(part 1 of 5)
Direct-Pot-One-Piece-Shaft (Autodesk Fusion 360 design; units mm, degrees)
parameter "FrameLength" = 640 comment "Fixed existing outer length"
parameter "FrameWidth" = 190 comment "Fixed existing outer width"
parameter "FrameHeight" = 110 comment "Fixed existing height"
parameter "PivotHeight" = 30 comment "Above frame center"
parameter "LeverTravel" = 100 comment "Stable endpoint to endpoint"
parameter "PrintClearance" = 0.3 comment "Prototype diametral running clearance"
base_mesh_feature "Base Mesh Feature"
ground "Pin1"
work_plane "WorkPlane1" AlongDistance -36 ExtraOffset 0
sketch "Flat load-bearing plate" plane through (-36, 0, 0) normal (1, 0, 0) x axis (0, 0, -1)
  line L1 (-33, -55) -> (-33, -75)
  line L2 (2, -55) -> (-33, -55)
  line L3 (2, 55) -> (2, -55)
  line L4 (-33, 55) -> (2, 55)
  line L5 (-33, 75) -> (-33, 55)
  line L6 (-57, 75) -> (-33, 75)
  line L7 (-57, 32) -> (-57, 75)
  line L8 (-86, 26) -> (-57, 32)
  line L9 (-86, -26) -> (-86, 26)
  line L10 (-57, -32) -> (-86, -26)
  line L11 (-57, -75) -> (-57, -32)
  line L12 (-33, -75) -> (-57, -75)
extrude "Extrude1" new body sketch "Flat load-bearing plate" along normal blind 12
work_plane "WorkPlane2" AlongDistance -37 ExtraOffset 0
sketch "Replaceable bushing seat" plane through (-37, 0, 0) normal (1, 0, 0) x axis (0, 0, -1)
  circle C1 centre (-65, 0) radius 10.15
extrude "Extrude2" cut sketch "Replaceable bushing seat" along normal blind 14
work_plane "WorkPlane3" AlongDistance -37 ExtraOffset 0
sketch "Follower pivot bolt" plane through (-37, 0, 0) normal (1, 0, 0) x axis (0, 0, -1)
  circle C1 centre (-12, -35) radius 2.7
extrude "Extrude3" cut sketch "Follower pivot bolt" along normal blind 14
work_plane "WorkPlane4" AlongDistance -76 ExtraOffset 0
sketch "M5 rail mounting bore" plane through (0, -76, 0) normal (0, 1, 0) x axis (1, 0, 0)
  circle C1 centre (-30, -45) radius 2.7
extrude "Extrude4" cut sketch "M5 rail mounting bore" along normal blind 22
work_plane "WorkPlane5" AlongDistance -55 ExtraOffset 0
sketch "Rail screw tool and washer access" plane through (0, -55, 0) normal (0, 1, 0) x axis (1, 0, 0)
  circle C1 centre (-30, -45) radius 5.3
extrude "Extrude5" cut sketch "Rail screw tool and washer access" along normal blind 12
work_plane "WorkPlane6" AlongDistance 54 ExtraOffset 0
sketch "M5 rail mounting bore (1)" plane through (0, 54, 0) normal (0, 1, 0) x axis (1, 0, 0)
  circle C1 centre (-30, -45) radius 2.7
extrude "Extrude6" cut sketch "M5 rail mounting bore (1)" along normal blind 22
work_plane "WorkPlane7" AlongDistance 43 ExtraOffset 0
sketch "Rail screw tool and washer access (1)" plane through (0, 43, 0) normal (0, 1, 0) x axis (1, 0, 0)
  circle C1 centre (-30, -45) radius 5.3
extrude "Extrude7" cut sketch "Rail screw tool and washer access (1)" along normal blind 12
work_plane "WorkPlane8" AlongDistance -37 ExtraOffset 0
sketch "Spring crossblock attachment" plane through (-37, 0, 0) normal (1, 0, 0) x axis (0, 0, -1)
  circle C1 centre (-44, -59) radius 1.7
extrude "Extrude8" cut sketch "Spring crossblock attachment" along normal blind 14
work_plane "WorkPlane9" AlongDistance -37 ExtraOffset 0
sketch "Spring crossblock attachment (1)" plane through (-37, 0, 0) normal (1, 0, 0) x axis (0, 0, -1)
  circle C1 centre (-44, -51) radius 1.7
extrude "Extrude9" cut sketch "Spring crossblock attachment (1)" along normal blind 14
work_plane "WorkPlane1" AlongDistance 24 ExtraOffset 0
sketch "Flat load-bearing plate" plane through (24, 0, 0) normal (1, 0, 0) x axis (0, 0, -1)
  line L1 (-33, -55) -> (-33, -75)
  line L2 (2, -55) -> (-33, -55)
  line L3 (2, 55) -> (2, -55)
  line L4 (-33, 55) -> (2, 55)
  line L5 (-33, 75) -> (-33, 55)
  line L6 (-57, 75) -> (-33, 75)
  line L7 (-57, 32) -> (-57, 75)
  line L8 (-86, 26) -> (-57, 32)
  line L9 (-86, -26) -> (-86, 26)
  line L10 (-57, -32) -> (-86, -26)
  line L11 (-57, -75) -> (-57, -32)
  line L12 (-33, -75) -> (-57, -75)
extrude "Extrude1" new body sketch "Flat load-bearing plate" along normal blind 12
work_plane "WorkPlane2" AlongDistance 23 ExtraOffset 0
sketch "Replaceable bushing seat" plane through (23, 0, 0) normal (1, 0, 0) x axis (0, 0, -1)
  circle C1 centre (-65, 0) radius 10.15
extrude "Extrude2" cut sketch "Replaceable bushing seat" along normal blind 14
work_plane "WorkPlane3" AlongDistance 23 ExtraOffset 0
sketch "Follower pivot bolt" plane through (23, 0, 0) normal (1, 0, 0) x axis (0, 0, -1)
  circle C1 centre (-12, -35) radius 2.7
extrude "Extrude3" cut sketch "Follower pivot bolt" along normal blind 14
work_plane "WorkPlane4" AlongDistance -76 ExtraOffset 0
sketch "M5 rail mounting bore" plane through (0, -76, 0) normal (0, 1, 0) x axis (1, 0, 0)
  circle C1 centre (30, -45) radius 2.7
extrude "Extrude4" cut sketch "M5 rail mounting bore" along normal blind 22
work_plane "WorkPlane5" AlongDistance -55 ExtraOffset 0
sketch "Rail screw tool and washer access" plane through (0, -55, 0) normal (0, 1, 0) x axis (1, 0, 0)
  circle C1 centre (30, -45) radius 5.3
extrude "Extrude5" cut sketch "Rail screw tool and washer access" along normal blind 12
work_plane "WorkPlane6" AlongDistance 54 ExtraOffset 0
sketch "M5 rail mounting bore (1)" plane through (0, 54, 0) normal (0, 1, 0) x axis (1, 0, 0)
  circle C1 centre (30, -45) radius 2.7
extrude "Extrude6" cut sketch "M5 rail mounting bore (1)" along normal blind 22
work_plane "WorkPlane7" AlongDistance 43 ExtraOffset 0
sketch "Rail screw tool and washer access (1)" plane through (0, 43, 0) normal (0, 1, 0) x axis (1, 0, 0)
  circle C1 centre (30, -45) radius 5.3
extrude "Extrude7" cut sketch "Rail screw tool and washer access (1)" along normal blind 12
work_plane "WorkPlane8" AlongDistance 23 ExtraOffset 0
sketch "Spring crossblock attachment" plane through (23, 0, 0) normal (1, 0, 0) x axis (0, 0, -1)
  circle C1 centre (-44, -59) radius 1.7
extrude "Extrude8" cut sketch "Spring crossblock attachment" along normal blind 14
work_plane "WorkPlane9" AlongDistance 23 ExtraOffset 0
sketch "Spring crossblock attachment (1)" plane through (23, 0, 0) normal (1, 0, 0) x axis (0, 0, -1)
  circle C1 centre (-44, -51) radius 1.7
extrude "Extrude9" cut sketch "Spring crossblock attachment (1)" along normal blind 14
work_plane "WorkPlane1" AlongDistance -36 ExtraOffset 0
sketch "Replaceable journal body" plane through (-36, 0, 0) normal (1, 0, 0) x axis (0, 0, -1)
  circle C1 centre (-65, 0) radius 10.05
extrude "Extrude1" new body sketch "Replaceable journal body" along normal blind 12 bodies "P03 Left flanged journal bush"
work_plane "WorkPlane2" AlongDistance -37.2 ExtraOffset 0
sketch "Axial thrust flange" plane through (-37.2, 0, 0) normal (1, 0, 0) x axis (0, 0, -1)
  circle C1 centre (-65, 0) radius 12.75
extrude "Extrude2" add sketch "Axial thrust flange" along normal blind 1.2
work_plane "WorkPlane3" AlongDistance -38 ExtraOffset 0
sketch "Running journal bore" plane through (-38, 0, 0) normal (1, 0, 0) x axis (0, 0, -1)
  circle C1 centre (-65, 0) radius 6.15
extrude "Extrude3" cut sketch "Running journal bore" along normal blind 15
work_plane "WorkPlane1" AlongDistance 24 ExtraOffset 0
sketch "Replaceable journal body" plane through (24, 0, 0) normal (1, 0, 0) x axis (0, 0, -1)
  circle C1 centre (-65, 0) radius 10.05
extrude "Extrude1" new body sketch "Replaceable journal body" along normal blind 12 bodies "P04 Right bush lower half"
work_plane "WorkPlane2" AlongDistance 36 ExtraOffset 0
sketch "Axial thrust flange" plane through (36, 0, 0) normal (1, 0, 0) x axis (0, 0, -1)
  circle C1 centre (-65, 0) radius 12.75
extrude "Extrude2" add sketch "Axial thrust flange" along normal blind 1.2
work_plane "WorkPlane3" AlongDistance 23 ExtraOffset 0
sketch "Running journal bore" plane through (23, 0, 0) normal (1, 0, 0) x axis (0, 0, -1)
  circle C1 centre (-65, 0) radius 6.15
extrude "Extrude3" cut sketch "Running journal bore" along normal blind 15
work_plane "WorkPlane1" AlongDistance -39.35 ExtraOffset 0
sketch "Axial cap" plane through (-39.35, 0, 0) normal (1, 0, 0) x axis (0, 0, -1)
  circle C1 centre (-65, 0) radius 10
extrude "Extrude1" new body sketch "Axial cap" along normal blind 2 bodies "P06 Shaft retaining cap"
work_plane "WorkPlane2" AlongDistance -39.5 ExtraOffset 0
sketch "M3 cap screw" plane through (-39.5, 0, 0) normal (1, 0, 0) x axis (0, 0, -1)
  circle C1 centre (-65, 0) radius 1.7
extrude "Extrude2" cut sketch "M3 cap screw" along normal blind 2.4
work_plane "WorkPlane1" AlongDistance -7 ExtraOffset 0
sketch "Main lever hub" plane through (-7, 0, 0) normal (1, 0, 0) x axis (0, 0, -1)
  circle C1 centre (-65, 0) radius 22
extrude "Extrude1" new body sketch "Main lever hub" along normal blind 14 bodies "P07 Integral lever rotor and cam carrier"
work_plane "WorkPlane2" AlongDistance -7 ExtraOffset 0
sketch "Continuous reinforced lever stem" plane through (-7, 0, 0) normal (1, 0, 0) x axis (0, 0, -1)
  line L1 (-60, 14) -> (-60, -14)
  line L2 (-95, 11) -> (-60, 14)
  line L3 (-150, 7) -> (-95, 11)
  line L4 (-195, 7) -> (-150, 7)
  line L5 (-195, -7) -> (-195, 7)
  line L6 (-150, -7) -> (-195, -7)
  line L7 (-95, -11) -> (-150, -7)
  line L8 (-60, -14) -> (-95, -11)
extrude "Extrude2" add sketch "Continuous reinforced lever stem" along normal blind 14
work_plane "WorkPlane3" AlongDistance -7 ExtraOffset 0
sketch "Integrated cam carrier fan" plane through (-7, 0, 0) normal (1, 0, 0) x axis (0, 0, -1)
  line L1 (-44.5, 35.507) -> (-65, 0)
  line L2 (-42.6698, 34.3855) -> (-44.5, 35.507)
  line L3 (-40.9008, 33.1697) -> (-42.6698, 34.3855)
  line L4 (-39.1979, 31.863) -> (-40.9008, 33.1697)
  line L5 (-37.5656, 30.4689) -> (-39.1979, 31.863)
  line L6 (-36.0086, 28.9914) -> (-37.5656, 30.4689)
  line L7 (-34.5311, 27.4344) -> (-36.0086, 28.9914)
  line L8 (-33.137, 25.8021) -> (-34.5311, 27.4344)
  line L9 (-31.8303, 24.0992) -> (-33.137, 25.8021)
  line L10 (-30.6145, 22.3302) -> (-31.8303, 24.0992)
  line L11 (-29.493, 20.5) -> (-30.6145, 22.3302)
  line L12 (-28.4687, 18.6136) -> (-29.493, 20.5)
  line L13 (-27.5446, 16.6762) -> (-28.4687, 18.6136)
  line L14 (-26.7232, 14.6931) -> (-27.5446, 16.6762)
  line L15 (-26.0067, 12.6697) -> (-26.7232, 14.6931)
  line L16 (-25.397, 10.6116) -> (-26.0067, 12.6697)
  line L17 (-24.8959, 8.5244) -> (-25.397, 10.6116)
  line L18 (-24.5048, 6.4138) -> (-24.8959, 8.5244)
  line L19 (-24.2246, 4.2857) -> (-24.5048, 6.4138)
  line L20 (-24.0562, 2.1458) -> (-24.2246, 4.2857)
  line L21 (-24, 0) -> (-24.0562, 2.1458)
  line L22 (-24.0562, -2.1458) -> (-24, 0)
  line L23 (-24.2246, -4.2857) -> (-24.0562, -2.1458)
  line L24 (-24.5048, -6.4138) -> (-24.2246, -4.2857)
  line L25 (-24.8959, -8.5244) -> (-24.5048, -6.4138)
  line L26 (-25.397, -10.6116) -> (-24.8959, -8.5244)
  line L27 (-26.0067, -12.6697) -> (-25.397, -10.6116)
  line L28 (-26.7232, -14.6931) -> (-26.0067, -12.6697)
  line L29 (-27.5446, -16.6762) -> (-26.7232, -14.6931)
  line L30 (-28.4687, -18.6136) -> (-27.5446, -16.6762)
  line L31 (-29.493, -20.5) -> (-28.4687, -18.6136)
  line L32 (-30.6145, -22.3302) -> (-29.493, -20.5)
  line L33 (-31.8303, -24.0992) -> (-30.6145, -22.3302)
  line L34 (-33.137, -25.8021) -> (-31.8303, -24.0992)
  line L35 (-34.5311, -27.4344) -> (-33.137, -25.8021)
  line L36 (-36.0086, -28.9914) -> (-34.5311, -27.4344)
  line L37 (-37.5656, -30.4689) -> (-36.0086, -28.9914)
  line L38 (-39.1979, -31.863) -> (-37.5656, -30.4689)
  line L39 (-40.9008, -33.1697) -> (-39.1979, -31.863)
  line L40 (-42.6698, -34.3855) -> (-40.9008, -33.1697)
  line L41 (-44.5, -35.507) -> (-42.6698, -34.3855)
  line L42 (-65, 0) -> (-44.5, -35.507)
extrude "Extrude3" add sketch "Integrated cam carrier fan" along normal blind 14
work_plane "WorkPlane4" AlongDistance -23.6 ExtraOffset 0
sketch "Integral axial locating hub" plane through (-23.6, 0, 0) normal (1, 0, 0) x axis (0, 0, -1)
  circle C1 centre (-65, 0) radius 10
work_plane "WorkPlane5" AlongDistance -24 ExtraOffset 0
sketch "D shaft socket" plane through (-24, 0, 0) normal (1, 0, 0) x axis (0, 0, -1)
  line L1 (-69.6247, 6.65) -> (-60.3753, 6.65)
  arc A1 centre (-65, 0) radius 8.1 clockwise from (-60.3753, 6.65) to (-69.6247, 6.65)
extrude "Extrude5" cut sketch "D shaft socket" along normal blind 48
work_plane "WorkPlane6" AlongDistance 0.3 ExtraOffset 0
sketch "Cam M3 insert pocket" plane through (0.3, 0, 0) normal (1, 0, 0) x axis (0, 0, -1)
  circle C1 centre (-39.5442, 25.4558) radius 1.7
extrude "Extrude6" cut sketch "Cam M3 insert pocket" along normal blind 6.8
work_plane "WorkPlane7" AlongDistance 0.3 ExtraOffset 0
sketch "Cam M3 insert pocket (1)" plane through (0.3, 0, 0) normal (1, 0, 0) x axis (0, 0, -1)
  circle C1 centre (-29, 0) radius 1.7
extrude "Extrude7" cut sketch "Cam M3 insert pocket (1)" along normal blind 6.8
work_plane "WorkPlane8" AlongDistance 0.3 ExtraOffset 0
sketch "Cam M3 insert pocket (2)" plane through (0.3, 0, 0) normal (1, 0, 0) x axis (0, 0, -1)
  circle C1 centre (-39.5442, -25.4558) radius 1.7
extrude "Extrude8" cut sketch "Cam M3 insert pocket (2)" along normal blind 6.8
work_plane "WorkPlane9" AlongDistance -8 ExtraOffset 0
sketch "Grip through bolt" plane through (-8, 0, 0) normal (1, 0, 0) x axis (0, 0, -1)
  circle C1 centre (-180, 0) radius 1.7
extrude "Extrude9" cut sketch "Grip through bolt" along normal blind 16
work_plane "WorkPlane10" AlongDistance -8 ExtraOffset 0
sketch "Grip through bolt (1)" plane through (-8, 0, 0) normal (1, 0, 0) x axis (0, 0, -1)
  circle C1 centre (-190, 0) radius 1.7
extrude "Extrude10" cut sketch "Grip through bolt (1)" along normal blind 16
work_plane "WorkPlane1" AlongDistance 7 ExtraOffset 0
sketch "Roller compensated replaceable cam" plane through (7, 0, 0) normal (1, 0, 0) x axis (0, 0, -1)
  line L1 (-39.4967, 42.2602) -> (-39.6212, 42.3096)
  line L2 (-39.3834, 42.211) -> (-39.4967, 42.2602)
  line L3 (-39.2796, 42.1617) -> (-39.3834, 42.211)
  line L4 (-39.1836, 42.1119) -> (-39.2796, 42.1617)
  line L5 (-39.0932, 42.0608) -> (-39.1836, 42.1119)
  line L6 (-39.0065, 42.0075) -> (-39.0932, 42.0608)
  line L7 (-38.9215, 41.9508) -> (-39.0065, 42.0075)
  line L8 (-38.8363, 41.8895) -> (-38.9215, 41.9508)
  line L9 (-38.7492, 41.8219) -> (-38.8363, 41.8895)
  line L10 (-38.6586, 41.7465) -> (-38.7492, 41.8219)
  line L11 (-38.5633, 41.6619) -> (-38.6586, 41.7465)
  line L12 (-38.4623, 41.5665) -> (-38.5633, 41.6619)
  line L13 (-38.3549, 41.459) -> (-38.4623, 41.5665)
  line L14 (-38.2404, 41.3384) -> (-38.3549, 41.459)
  line L15 (-38.1184, 41.204) -> (-38.2404, 41.3384)
  line L16 (-37.9886, 41.055) -> (-38.1184, 41.204)
  line L17 (-37.8508, 40.8913) -> (-37.9886, 41.055)
  line L18 (-37.7045, 40.7127) -> (-37.8508, 40.8913)
  line L19 (-37.5496, 40.5196) -> (-37.7045, 40.7127)
  line L20 (-37.3856, 40.3123) -> (-37.5496, 40.5196)
  line L21 (-37.2122, 40.0915) -> (-37.3856, 40.3123)
  line L22 (-37.0289, 39.858) -> (-37.2122, 40.0915)
  line L23 (-36.8353, 39.6128) -> (-37.0289, 39.858)
  line L24 (-36.6306, 39.3571) -> (-36.8353, 39.6128)
  line L25 (-36.4145, 39.0923) -> (-36.6306, 39.3571)
  line L26 (-36.1865, 38.82) -> (-36.4145, 39.0923)
  line L27 (-35.9461, 38.5417) -> (-36.1865, 38.82)
  line L28 (-35.6932, 38.2594) -> (-35.9461, 38.5417)
  line L29 (-35.4277, 37.9751) -> (-35.6932, 38.2594)
  line L30 (-35.15, 37.6908) -> (-35.4277, 37.9751)
  line L31 (-34.8607, 37.4087) -> (-35.15, 37.6908)
  line L32 (-34.5606, 37.1307) -> (-34.8607, 37.4087)
  line L33 (-34.2512, 36.859) -> (-34.5606, 37.1307)
  line L34 (-33.934, 36.5953) -> (-34.2512, 36.859)
  line L35 (-33.6109, 36.341) -> (-33.934, 36.5953)
  line L36 (-33.2841, 36.0975) -> (-33.6109, 36.341)
  line L37 (-32.9558, 35.8655) -> (-33.2841, 36.0975)
  line L38 (-32.6282, 35.6454) -> (-32.9558, 35.8655)
  line L39 (-32.3036, 35.4375) -> (-32.6282, 35.6454)
  line L40 (-31.984, 35.2415) -> (-32.3036, 35.4375)
  line L41 (-31.6712, 35.057) -> (-31.984, 35.2415)
  line L42 (-31.3671, 34.8833) -> (-31.6712, 35.057)
  line L43 (-31.073, 34.7197) -> (-31.3671, 34.8833)
  line L44 (-30.7902, 34.5655) -> (-31.073, 34.7197)
  line L45 (-30.52, 34.4197) -> (-30.7902, 34.5655)
  line L46 (-30.263, 34.2816) -> (-30.52, 34.4197)
  line L47 (-30.0201, 34.1506) -> (-30.263, 34.2816)
  line L48 (-29.7919, 34.0259) -> (-30.0201, 34.1506)
  line L49 (-29.5787, 33.9071) -> (-29.7919, 34.0259)
  line L50 (-29.3807, 33.7939) -> (-29.5787, 33.9071)
  line L51 (-29.1982, 33.6858) -> (-29.3807, 33.7939)
  line L52 (-29.0309, 33.5827) -> (-29.1982, 33.6858)
  line L53 (-28.8786, 33.4843) -> (-29.0309, 33.5827)
  line L54 (-28.7406, 33.3906) -> (-28.8786, 33.4843)
  line L55 (-28.6164, 33.3013) -> (-28.7406, 33.3906)
  line L56 (-28.5047, 33.2161) -> (-28.6164, 33.3013)
  line L57 (-28.4046, 33.1346) -> (-28.5047, 33.2161)
  line L58 (-28.3144, 33.0563) -> (-28.4046, 33.1346)
  line L59 (-28.2327, 32.9802) -> (-28.3144, 33.0563)
  line L60 (-28.1577, 32.9052) -> (-28.2327, 32.9802)
  line L61 (-28.0879, 32.8301) -> (-28.1577, 32.9052)
  line L62 (-28.0214, 32.7532) -> (-28.0879, 32.8301)
  line L63 (-27.9569, 32.6728) -> (-28.0214, 32.7532)
  line L64 (-27.893, 32.5869) -> (-27.9569, 32.6728)
  line L65 (-27.8285, 32.4936) -> (-27.893, 32.5869)
  line L66 (-27.7627, 32.3911) -> (-27.8285, 32.4936)
  line L67 (-27.6947, 32.2776) -> (-27.7627, 32.3911)
  line L68 (-27.6241, 32.1514) -> (-27.6947, 32.2776)
  line L69 (-27.5507, 32.0113) -> (-27.6241, 32.1514)
  line L70 (-27.4742, 31.8562) -> (-27.5507, 32.0113)
  line L71 (-27.3945, 31.6853) -> (-27.4742, 31.8562)
  line L72 (-27.3113, 31.4981) -> (-27.3945, 31.6853)
  line L73 (-27.2245, 31.2943) -> (-27.3113, 31.4981)
  line L74 (-27.1338, 31.074) -> (-27.2245, 31.2943)
  line L75 (-27.0388, 30.8373) -> (-27.1338, 31.074)
  line L76 (-26.939, 30.5847) -> (-27.0388, 30.8373)
  line L77 (-26.8337, 30.3166) -> (-26.939, 30.5847)
  line L78 (-26.7223, 30.034) -> (-26.8337, 30.3166)
  line L79 (-26.6038, 29.7375) -> (-26.7223, 30.034)
  line L80 (-26.4775, 29.4284) -> (-26.6038, 29.7375)
  line L81 (-26.3424, 29.1079) -> (-26.4775, 29.4284)
  line L82 (-26.1977, 28.7772) -> (-26.3424, 29.1079)
  line L83 (-26.0425, 28.4382) -> (-26.1977, 28.7772)
  line L84 (-25.8761, 28.0925) -> (-26.0425, 28.4382)
  line L85 (-25.6981, 27.7422) -> (-25.8761, 28.0925)
  line L86 (-25.5084, 27.3893) -> (-25.6981, 27.7422)
  line L87 (-25.3069, 27.0362) -> (-25.5084, 27.3893)
  line L88 (-25.0943, 26.6851) -> (-25.3069, 27.0362)
  line L89 (-24.8713, 26.3382) -> (-25.0943, 26.6851)
  line L90 (-24.6392, 25.9976) -> (-24.8713, 26.3382)
  line L91 (-24.3995, 25.6653) -> (-24.6392, 25.9976)
  line L92 (-24.1539, 25.3428) -> (-24.3995, 25.6653)
  line L93 (-23.9045, 25.0314) -> (-24.1539, 25.3428)
  line L94 (-23.6532, 24.7321) -> (-23.9045, 25.0314)
  line L95 (-23.4022, 24.4455) -> (-23.6532, 24.7321)
  line L96 (-23.1534, 24.1718) -> (-23.4022, 24.4455)
  line L97 (-22.9088, 23.9111) -> (-23.1534, 24.1718)
  line L98 (-22.6701, 23.6631) -> (-22.9088, 23.9111)
  line L99 (-22.4387, 23.4276) -> (-22.6701, 23.6631)
  line L100 (-22.2162, 23.204) -> (-22.4387, 23.4276)
  line L101 (-22.0036, 22.9918) -> (-22.2162, 23.204)
  line L102 (-21.8021, 22.7907) -> (-22.0036, 22.9918)
  line L103 (-21.6123, 22.6001) -> (-21.8021, 22.7907)
  line L104 (-21.435, 22.4197) -> (-21.6123, 22.6001)
  line L105 (-21.2706, 22.2491) -> (-21.435, 22.4197)
  line L106 (-21.1193, 22.088) -> (-21.2706, 22.2491)
  line L107 (-20.9813, 21.9362) -> (-21.1193, 22.088)
  line L108 (-20.8565, 21.7934) -> (-20.9813, 21.9362)
  line L109 (-20.7443, 21.6594) -> (-20.8565, 21.7934)
  line L110 (-20.6444, 21.5337) -> (-20.7443, 21.6594)
  line L111 (-20.556, 21.4159) -> (-20.6444, 21.5337)
  line L112 (-20.478, 21.3055) -> (-20.556, 21.4159)
  line L113 (-20.4094, 21.2014) -> (-20.478, 21.3055)
  line L114 (-20.349, 21.1027) -> (-20.4094, 21.2014)
  line L115 (-20.2954, 21.0079) -> (-20.349, 21.1027)
  line L116 (-20.2475, 20.9154) -> (-20.2954, 21.0079)
  line L117 (-20.2039, 20.8234) -> (-20.2475, 20.9154)
  line L118 (-20.1637, 20.7297) -> (-20.2039, 20.8234)
  line L119 (-20.126, 20.6321) -> (-20.1637, 20.7297)
  line L120 (-20.0901, 20.5286) -> (-20.126, 20.6321)
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extrude "Extrude1" new body sketch "Roller compensated replaceable cam" along normal blind 8 bodies "P08 Cam 7 gates - stable endpoints"
work_plane "WorkPlane2" AlongDistance 6.9 ExtraOffset 0
sketch "Cam screw clearance" plane through (6.9, 0, 0) normal (1, 0, 0) x axis (0, 0, -1)
  circle C1 centre (-39.5442, 25.4558) radius 1.7
extrude "Extrude2" cut sketch "Cam screw clearance" along normal blind 8.2
work_plane "WorkPlane3" AlongDistance 12 ExtraOffset 0
sketch "Cam head recess" plane through (12, 0, 0) normal (1, 0, 0) x axis (0, 0, -1)
  circle C1 centre (-39.5442, 25.4558) radius 3.1
extrude "Extrude3" cut sketch "Cam head recess" along normal blind 3.1
work_plane "WorkPlane4" AlongDistance 6.9 ExtraOffset 0
sketch "Cam screw clearance (1)" plane through (6.9, 0, 0) normal (1, 0, 0) x axis (0, 0, -1)
  circle C1 centre (-29, 0) radius 1.7
extrude "Extrude4" cut sketch "Cam screw clearance (1)" along normal blind 8.2
work_plane "WorkPlane5" AlongDistance 12 ExtraOffset 0
sketch "Cam head recess (1)" plane through (12, 0, 0) normal (1, 0, 0) x axis (0, 0, -1)
  circle C1 centre (-29, 0) radius 3.1
extrude "Extrude5" cut sketch "Cam head recess (1)" along normal blind 3.1
work_plane "WorkPlane6" AlongDistance 6.9 ExtraOffset 0
sketch "Cam screw clearance (2)" plane through (6.9, 0, 0) normal (1, 0, 0) x axis (0, 0, -1)
  circle C1 centre (-39.5442, -25.4558) radius 1.7
extrude "Extrude6" cut sketch "Cam screw clearance (2)" along normal blind 8.2
work_plane "WorkPlane7" AlongDistance 12 ExtraOffset 0
sketch "Cam head recess (2)" plane through (12, 0, 0) normal (1, 0, 0) x axis (0, 0, -1)
  circle C1 centre (-39.5442, -25.4558) radius 3.1
extrude "Extrude7" cut sketch "Cam head recess (2)" along normal blind 3.1
work_plane "WorkPlane1" AlongDistance 7 ExtraOffset 0
sketch "Roller compensated replaceable cam" plane through (7, 0, 0) normal (1, 0, 0) x axis (0, 0, -1)
  line L1 (-40.6423, 42.8316) -> (-40.8055, 42.9534)
  line L2 (-40.4783, 42.705) -> (-40.6423, 42.8316)
  line L3 (-40.3132, 42.5736) -> (-40.4783, 42.705)
  line L4 (-40.1469, 42.4372) -> (-40.3132, 42.5736)
  line L5 (-39.9791, 42.2958) -> (-40.1469, 42.4372)
  line L6 (-39.8097, 42.1493) -> (-39.9791, 42.2958)
  line L7 (-39.6386, 41.9977) -> (-39.8097, 42.1493)
  line L8 (-39.4656, 41.8411) -> (-39.6386, 41.9977)
  line L9 (-39.2906, 41.6794) -> (-39.4656, 41.8411)
  line L10 (-39.1134, 41.5128) -> (-39.2906, 41.6794)
  line L11 (-38.9338, 41.3413) -> (-39.1134, 41.5128)
  line L12 (-38.7519, 41.165) -> (-38.9338, 41.3413)
  line L13 (-38.5674, 40.9842) -> (-38.7519, 41.165)
  line L14 (-38.3803, 40.7991) -> (-38.5674, 40.9842)
  line L15 (-38.1904, 40.6097) -> (-38.3803, 40.7991)
  line L16 (-37.9976, 40.4164) -> (-38.1904, 40.6097)
  line L17 (-37.8019, 40.2195) -> (-37.9976, 40.4164)
  line L18 (-37.6031, 40.0191) -> (-37.8019, 40.2195)
  line L19 (-37.4011, 39.8157) -> (-37.6031, 40.0191)
  line L20 (-37.1958, 39.6094) -> (-37.4011, 39.8157)
  line L21 (-36.9872, 39.4008) -> (-37.1958, 39.6094)
  line L22 (-36.7753, 39.19) -> (-36.9872, 39.4008)
  line L23 (-36.5599, 38.9775) -> (-36.7753, 39.19)
  line L24 (-36.3411, 38.7636) -> (-36.5599, 38.9775)
  line L25 (-36.1189, 38.5488) -> (-36.3411, 38.7636)
  line L26 (-35.8933, 38.3333) -> (-36.1189, 38.5488)
  line L27 (-35.6644, 38.1177) -> (-35.8933, 38.3333)
  line L28 (-35.4322, 37.9021) -> (-35.6644, 38.1177)
  line L29 (-35.197, 37.6871) -> (-35.4322, 37.9021)
  line L30 (-34.9588, 37.473) -> (-35.197, 37.6871)
  line L31 (-34.7178, 37.2602) -> (-34.9588, 37.473)
  line L32 (-34.4743, 37.0489) -> (-34.7178, 37.2602)
  line L33 (-34.2286, 36.8395) -> (-34.4743, 37.0489)
  line L34 (-33.9808, 36.6322) -> (-34.2286, 36.8395)
  line L35 (-33.7314, 36.4274) -> (-33.9808, 36.6322)
  line L36 (-33.4806, 36.2252) -> (-33.7314, 36.4274)
  line L37 (-33.2289, 36.0258) -> (-33.4806, 36.2252)
  line L38 (-32.9765, 35.8294) -> (-33.2289, 36.0258)
  line L39 (-32.7239, 35.6361) -> (-32.9765, 35.8294)
  line L40 (-32.4714, 35.446) -> (-32.7239, 35.6361)
  line L41 (-32.2195, 35.259) -> (-32.4714, 35.446)
  line L42 (-31.9685, 35.0753) -> (-32.2195, 35.259)
  line L43 (-31.7188, 34.8948) -> (-31.9685, 35.0753)
  line L44 (-31.4708, 34.7175) -> (-31.7188, 34.8948)
  line L45 (-31.2249, 34.5432) -> (-31.4708, 34.7175)
  line L46 (-30.9813, 34.3719) -> (-31.2249, 34.5432)
  line L47 (-30.7405, 34.2034) -> (-30.9813, 34.3719)
  line L48 (-30.5027, 34.0377) -> (-30.7405, 34.2034)
  line L49 (-30.2682, 33.8746) -> (-30.5027, 34.0377)
  line L50 (-30.0373, 33.7139) -> (-30.2682, 33.8746)
  line L51 (-29.8103, 33.5555) -> (-30.0373, 33.7139)
  line L52 (-29.5875, 33.3992) -> (-29.8103, 33.5555)
  line L53 (-29.3689, 33.2448) -> (-29.5875, 33.3992)
  line L54 (-29.1548, 33.0923) -> (-29.3689, 33.2448)
  line L55 (-28.9455, 32.9414) -> (-29.1548, 33.0923)
  line L56 (-28.7409, 32.7921) -> (-28.9455, 32.9414)
  line L57 (-28.5413, 32.644) -> (-28.7409, 32.7921)
  line L58 (-28.3468, 32.4972) -> (-28.5413, 32.644)
  line L59 (-28.1574, 32.3515) -> (-28.3468, 32.4972)
  line L60 (-27.9732, 32.2068) -> (-28.1574, 32.3515)
  line L61 (-27.7942, 32.0628) -> (-27.9732, 32.2068)
  line L62 (-27.6204, 31.9196) -> (-27.7942, 32.0628)
  line L63 (-27.4518, 31.7769) -> (-27.6204, 31.9196)
  line L64 (-27.2884, 31.6347) -> (-27.4518, 31.7769)
  line L65 (-27.1301, 31.4927) -> (-27.2884, 31.6347)
  line L66 (-26.9767, 31.351) -> (-27.1301, 31.4927)
  line L67 (-26.8282, 31.2092) -> (-26.9767, 31.351)
  line L68 (-26.6843, 31.0673) -> (-26.8282, 31.2092)
  line L69 (-26.545, 30.925) -> (-26.6843, 31.0673)
  line L70 (-26.4101, 30.7822) -> (-26.545, 30.925)
  line L71 (-26.2793, 30.6387) -> (-26.4101, 30.7822)
  line L72 (-26.1524, 30.4942) -> (-26.2793, 30.6387)
  line L73 (-26.0293, 30.3485) -> (-26.1524, 30.4942)
  line L74 (-25.9096, 30.2013) -> (-26.0293, 30.3485)
  line L75 (-25.7932, 30.0524) -> (-25.9096, 30.2013)
  line L76 (-25.6797, 29.9015) -> (-25.7932, 30.0524)
  line L77 (-25.5691, 29.7482) -> (-25.6797, 29.9015)
  line L78 (-25.461, 29.5923) -> (-25.5691, 29.7482)
  line L79 (-25.3553, 29.4334) -> (-25.461, 29.5923)
  line L80 (-25.2517, 29.2713) -> (-25.3553, 29.4334)
  line L81 (-25.15, 29.1057) -> (-25.2517, 29.2713)
  line L82 (-25.0502, 28.9363) -> (-25.15, 29.1057)
  line L83 (-24.9519, 28.7628) -> (-25.0502, 28.9363)
  line L84 (-24.855, 28.5849) -> (-24.9519, 28.7628)
  line L85 (-24.7595, 28.4024) -> (-24.855, 28.5849)
  line L86 (-24.665, 28.2152) -> (-24.7595, 28.4024)
  line L87 (-24.5716, 28.023) -> (-24.665, 28.2152)
  line L88 (-24.4791, 27.8257) -> (-24.5716, 28.023)
  line L89 (-24.3873, 27.6231) -> (-24.4791, 27.8257)
  line L90 (-24.2961, 27.4152) -> (-24.3873, 27.6231)
  line L91 (-24.2054, 27.2019) -> (-24.2961, 27.4152)
  line L92 (-24.115, 26.9832) -> (-24.2054, 27.2019)
  line L93 (-24.0247, 26.7591) -> (-24.115, 26.9832)
  line L94 (-23.9346, 26.5296) -> (-24.0247, 26.7591)
  line L95 (-23.8442, 26.2947) -> (-23.9346, 26.5296)
  line L96 (-23.7536, 26.0546) -> (-23.8442, 26.2947)
  line L97 (-23.6625, 25.8094) -> (-23.7536, 26.0546)
  line L98 (-23.5707, 25.5592) -> (-23.6625, 25.8094)
  line L99 (-23.478, 25.3041) -> (-23.5707, 25.5592)
  line L100 (-23.3842, 25.0444) -> (-23.478, 25.3041)
  line L101 (-23.2891, 24.7802) -> (-23.3842, 25.0444)
  line L102 (-23.1926, 24.5118) -> (-23.2891, 24.7802)
  line L103 (-23.0943, 24.2394) -> (-23.1926, 24.5118)
  line L104 (-22.9942, 23.9633) -> (-23.0943, 24.2394)
  line L105 (-22.8919, 23.6838) -> (-22.9942, 23.9633)
  line L106 (-22.7873, 23.4012) -> (-22.8919, 23.6838)
  line L107 (-22.6803, 23.1157) -> (-22.7873, 23.4012)
  line L108 (-22.5706, 22.8278) -> (-22.6803, 23.1157)
  line L109 (-22.4581, 22.5379) -> (-22.5706, 22.8278)
  line L110 (-22.3428, 22.2461) -> (-22.4581, 22.5379)
  line L111 (-22.2245, 21.953) -> (-22.3428, 22.2461)
  line L112 (-22.1031, 21.659) -> (-22.2245, 21.953)
  line L113 (-21.9788, 21.3644) -> (-22.1031, 21.659)
  line L114 (-21.8513, 21.0696) -> (-21.9788, 21.3644)
  line L115 (-21.7209, 20.7751) -> (-21.8513, 21.0696)
  line L116 (-21.5876, 20.4811) -> (-21.7209, 20.7751)
  line L117 (-21.4516, 20.1882) -> (-21.5876, 20.4811)
  line L118 (-21.3129, 19.8966) -> (-21.4516, 20.1882)
  line L119 (-21.1718, 19.6067) -> (-21.3129, 19.8966)
  line L120 (-21.0286, 19.3189) -> (-21.1718, 19.6067)
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extrude "Extrude1" new body sketch "Roller compensated replaceable cam" along normal blind 8 bodies "P08 Cam 5 gates - stable endpoints"
work_plane "WorkPlane2" AlongDistance 6.9 ExtraOffset 0
sketch "Cam screw clearance" plane through (6.9, 0, 0) normal (1, 0, 0) x axis (0, 0, -1)
  circle C1 centre (-39.5442, 25.4558) radius 1.7
extrude "Extrude2" cut sketch "Cam screw clearance" along normal blind 8.2
work_plane "WorkPlane3" AlongDistance 12 ExtraOffset 0
sketch "Cam head recess" plane through (12, 0, 0) normal (1, 0, 0) x axis (0, 0, -1)
  circle C1 centre (-39.5442, 25.4558) radius 3.1
extrude "Extrude3" cut sketch "Cam head recess" along normal blind 3.1
work_plane "WorkPlane4" AlongDistance 6.9 ExtraOffset 0
sketch "Cam screw clearance (1)" plane through (6.9, 0, 0) normal (1, 0, 0) x axis (0, 0, -1)
  circle C1 centre (-29, 0) radius 1.7
extrude "Extrude4" cut sketch "Cam screw clearance (1)" along normal blind 8.2
work_plane "WorkPlane5" AlongDistance 12 ExtraOffset 0
sketch "Cam head recess (1)" plane through (12, 0, 0) normal (1, 0, 0) x axis (0, 0, -1)
  circle C1 centre (-29, 0) radius 3.1
extrude "Extrude5" cut sketch "Cam head recess (1)" along normal blind 3.1
work_plane "WorkPlane6" AlongDistance 6.9 ExtraOffset 0
sketch "Cam screw clearance (2)" plane through (6.9, 0, 0) normal (1, 0, 0) x axis (0, 0, -1)
  circle C1 centre (-39.5442, -25.4558) radius 1.7
extrude "Extrude6" cut sketch "Cam screw clearance (2)" along normal blind 8.2
work_plane "WorkPlane7" AlongDistance 12 ExtraOffset 0
sketch "Cam head recess (2)" plane through (12, 0, 0) normal (1, 0, 0) x axis (0, 0, -1)
  circle C1 centre (-39.5442, -25.4558) radius 3.1
extrude "Extrude7" cut sketch "Cam head recess (2)" along normal blind 3.1
work_plane "WorkPlane1" AlongDistance 7 ExtraOffset 0
sketch "Roller compensated replaceable cam" plane through (7, 0, 0) normal (1, 0, 0) x axis (0, 0, -1)
  line L1 (-40.92, 42.0772) -> (-41.1325, 42.2273)
  line L2 (-40.7077, 41.9259) -> (-40.92, 42.0772)
  line L3 (-40.4956, 41.7734) -> (-40.7077, 41.9259)
  line L4 (-40.2838, 41.6199) -> (-40.4956, 41.7734)
  line L5 (-40.0721, 41.4654) -> (-40.2838, 41.6199)
  line L6 (-39.8606, 41.3098) -> (-40.0721, 41.4654)
  line L7 (-39.6492, 41.1532) -> (-39.8606, 41.3098)
  line L8 (-39.4381, 40.9957) -> (-39.6492, 41.1532)
  line L9 (-39.2271, 40.8372) -> (-39.4381, 40.9957)
  line L10 (-39.0163, 40.6779) -> (-39.2271, 40.8372)
  line L11 (-38.8057, 40.5176) -> (-39.0163, 40.6779)
  line L12 (-38.5952, 40.3566) -> (-38.8057, 40.5176)
  line L13 (-38.3849, 40.1947) -> (-38.5952, 40.3566)
  line L14 (-38.1747, 40.032) -> (-38.3849, 40.1947)
  line L15 (-37.9647, 39.8686) -> (-38.1747, 40.032)
  line L16 (-37.7549, 39.7045) -> (-37.9647, 39.8686)
  line L17 (-37.5452, 39.5397) -> (-37.7549, 39.7045)
  line L18 (-37.3357, 39.3742) -> (-37.5452, 39.5397)
  line L19 (-37.1263, 39.2081) -> (-37.3357, 39.3742)
  line L20 (-36.9171, 39.0413) -> (-37.1263, 39.2081)
  line L21 (-36.7081, 38.874) -> (-36.9171, 39.0413)
  line L22 (-36.4992, 38.7061) -> (-36.7081, 38.874)
  line L23 (-36.2905, 38.5376) -> (-36.4992, 38.7061)
  line L24 (-36.082, 38.3687) -> (-36.2905, 38.5376)
  line L25 (-35.8737, 38.1992) -> (-36.082, 38.3687)
  line L26 (-35.6656, 38.0292) -> (-35.8737, 38.1992)
  line L27 (-35.4577, 37.8588) -> (-35.6656, 38.0292)
  line L28 (-35.25, 37.688) -> (-35.4577, 37.8588)
  line L29 (-35.0425, 37.5167) -> (-35.25, 37.688)
  line L30 (-34.8352, 37.3451) -> (-35.0425, 37.5167)
  line L31 (-34.6282, 37.173) -> (-34.8352, 37.3451)
  line L32 (-34.4215, 37.0006) -> (-34.6282, 37.173)
  line L33 (-34.215, 36.8278) -> (-34.4215, 37.0006)
  line L34 (-34.0088, 36.6547) -> (-34.215, 36.8278)
  line L35 (-33.8028, 36.4812) -> (-34.0088, 36.6547)
  line L36 (-33.5972, 36.3074) -> (-33.8028, 36.4812)
  line L37 (-33.392, 36.1333) -> (-33.5972, 36.3074)
  line L38 (-33.187, 35.9589) -> (-33.392, 36.1333)
  line L39 (-32.9825, 35.7842) -> (-33.187, 35.9589)
  line L40 (-32.7783, 35.6093) -> (-32.9825, 35.7842)
  line L41 (-32.5745, 35.434) -> (-32.7783, 35.6093)
  line L42 (-32.3711, 35.2584) -> (-32.5745, 35.434)
  line L43 (-32.1682, 35.0826) -> (-32.3711, 35.2584)
  line L44 (-31.9657, 34.9065) -> (-32.1682, 35.0826)
  line L45 (-31.7637, 34.7302) -> (-31.9657, 34.9065)
  line L46 (-31.5623, 34.5535) -> (-31.7637, 34.7302)
  line L47 (-31.3613, 34.3766) -> (-31.5623, 34.5535)
  line L48 (-31.1609, 34.1994) -> (-31.3613, 34.3766)
  line L49 (-30.9611, 34.0219) -> (-31.1609, 34.1994)
  line L50 (-30.7619, 33.8442) -> (-30.9611, 34.0219)
  line L51 (-30.5634, 33.6662) -> (-30.7619, 33.8442)
  line L52 (-30.3654, 33.4878) -> (-30.5634, 33.6662)
  line L53 (-30.1682, 33.3092) -> (-30.3654, 33.4878)
  line L54 (-29.9717, 33.1303) -> (-30.1682, 33.3092)
  line L55 (-29.7759, 32.9511) -> (-29.9717, 33.1303)
  line L56 (-29.5809, 32.7715) -> (-29.7759, 32.9511)
  line L57 (-29.3866, 32.5916) -> (-29.5809, 32.7715)
  line L58 (-29.1932, 32.4114) -> (-29.3866, 32.5916)
  line L59 (-29.0007, 32.2308) -> (-29.1932, 32.4114)
  line L60 (-28.809, 32.0499) -> (-29.0007, 32.2308)
  line L61 (-28.6182, 31.8686) -> (-28.809, 32.0499)
  line L62 (-28.4284, 31.6869) -> (-28.6182, 31.8686)
  line L63 (-28.2395, 31.5048) -> (-28.4284, 31.6869)
  line L64 (-28.0516, 31.3224) -> (-28.2395, 31.5048)
  line L65 (-27.8647, 31.1395) -> (-28.0516, 31.3224)
  line L66 (-27.6789, 30.9562) -> (-27.8647, 31.1395)
  line L67 (-27.4942, 30.7724) -> (-27.6789, 30.9562)
  line L68 (-27.3106, 30.5882) -> (-27.4942, 30.7724)
  line L69 (-27.1281, 30.4035) -> (-27.3106, 30.5882)
  line L70 (-26.9468, 30.2184) -> (-27.1281, 30.4035)
  line L71 (-26.7667, 30.0327) -> (-26.9468, 30.2184)
  line L72 (-26.5878, 29.8465) -> (-26.7667, 30.0327)
  line L73 (-26.4102, 29.6599) -> (-26.5878, 29.8465)
  line L74 (-26.2338, 29.4727) -> (-26.4102, 29.6599)
  line L75 (-26.0588, 29.2849) -> (-26.2338, 29.4727)
  line L76 (-25.8851, 29.0966) -> (-26.0588, 29.2849)
  line L77 (-25.7127, 28.9078) -> (-25.8851, 29.0966)
  line L78 (-25.5418, 28.7183) -> (-25.7127, 28.9078)
  line L79 (-25.3723, 28.5283) -> (-25.5418, 28.7183)
  line L80 (-25.2042, 28.3376) -> (-25.3723, 28.5283)
  line L81 (-25.0376, 28.1464) -> (-25.2042, 28.3376)
  line L82 (-24.8725, 27.9545) -> (-25.0376, 28.1464)
  line L83 (-24.7089, 27.762) -> (-24.8725, 27.9545)
  line L84 (-24.5469, 27.5688) -> (-24.7089, 27.762)
  line L85 (-24.3864, 27.375) -> (-24.5469, 27.5688)
  line L86 (-24.2275, 27.1805) -> (-24.3864, 27.375)
  line L87 (-24.0703, 26.9854) -> (-24.2275, 27.1805)
  line L88 (-23.9146, 26.7895) -> (-24.0703, 26.9854)
  line L89 (-23.7607, 26.593) -> (-23.9146, 26.7895)
  line L90 (-23.6084, 26.3958) -> (-23.7607, 26.593)
  line L91 (-23.4578, 26.1978) -> (-23.6084, 26.3958)
  line L92 (-23.3089, 25.9992) -> (-23.4578, 26.1978)
  line L93 (-23.1618, 25.7998) -> (-23.3089, 25.9992)
  line L94 (-23.0164, 25.5997) -> (-23.1618, 25.7998)
  line L95 (-22.8728, 25.3988) -> (-23.0164, 25.5997)
  line L96 (-22.7309, 25.1972) -> (-22.8728, 25.3988)
  line L97 (-22.5909, 24.9949) -> (-22.7309, 25.1972)
  line L98 (-22.4527, 24.7917) -> (-22.5909, 24.9949)
  line L99 (-22.3163, 24.5879) -> (-22.4527, 24.7917)
  line L100 (-22.1817, 24.3832) -> (-22.3163, 24.5879)
  line L101 (-22.049, 24.1778) -> (-22.1817, 24.3832)
  line L102 (-21.9182, 23.9716) -> (-22.049, 24.1778)
  line L103 (-21.7892, 23.7646) -> (-21.9182, 23.9716)
  line L104 (-21.6622, 23.5568) -> (-21.7892, 23.7646)
  line L105 (-21.537, 23.3482) -> (-21.6622, 23.5568)
  line L106 (-21.4137, 23.1388) -> (-21.537, 23.3482)
  line L107 (-21.2923, 22.9286) -> (-21.4137, 23.1388)
  line L108 (-21.1728, 22.7176) -> (-21.2923, 22.9286)
  line L109 (-21.0553, 22.5058) -> (-21.1728, 22.7176)
  line L110 (-20.9397, 22.2931) -> (-21.0553, 22.5058)
  line L111 (-20.8259, 22.0796) -> (-20.9397, 22.2931)
  line L112 (-20.7142, 21.8653) -> (-20.8259, 22.0796)
  line L113 (-20.6043, 21.6502) -> (-20.7142, 21.8653)
  line L114 (-20.4964, 21.4342) -> (-20.6043, 21.6502)
  line L115 (-20.3904, 21.2174) -> (-20.4964, 21.4342)
  line L116 (-20.2863, 20.9997) -> (-20.3904, 21.2174)
  line L117 (-20.1842, 20.7812) -> (-20.2863, 20.9997)
  line L118 (-20.0839, 20.5618) -> (-20.1842, 20.7812)
  line L119 (-19.9856, 20.3416) -> (-20.0839, 20.5618)
  line L120 (-19.8892, 20.1205) -> (-19.9856, 20.3416)
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extrude "Extrude1" new body sketch "Roller compensated replaceable cam" along normal blind 8 bodies "P08 Cam 3 gates - stable endpoints"
work_plane "WorkPlane2" AlongDistance 6.9 ExtraOffset 0
sketch "Cam screw clearance" plane through (6.9, 0, 0) normal (1, 0, 0) x axis (0, 0, -1)
  circle C1 centre (-39.5442, 25.4558) radius 1.7
extrude "Extrude2" cut sketch "Cam screw clearance" along normal blind 8.2
work_plane "WorkPlane3" AlongDistance 12 ExtraOffset 0
sketch "Cam head recess" plane through (12, 0, 0) normal (1, 0, 0) x axis (0, 0, -1)
  circle C1 centre (-39.5442, 25.4558) radius 3.1
extrude "Extrude3" cut sketch "Cam head recess" along normal blind 3.1
work_plane "WorkPlane4" AlongDistance 6.9 ExtraOffset 0
sketch "Cam screw clearance (1)" plane through (6.9, 0, 0) normal (1, 0, 0) x axis (0, 0, -1)
  circle C1 centre (-29, 0) radius 1.7
extrude "Extrude4" cut sketch "Cam screw clearance (1)" along normal blind 8.2
work_plane "WorkPlane5" AlongDistance 12 ExtraOffset 0
sketch "Cam head recess (1)" plane through (12, 0, 0) normal (1, 0, 0) x axis (0, 0, -1)
  circle C1 centre (-29, 0) radius 3.1
extrude "Extrude5" cut sketch "Cam head recess (1)" along normal blind 3.1
work_plane "WorkPlane6" AlongDistance 6.9 ExtraOffset 0
sketch "Cam screw clearance (2)" plane through (6.9, 0, 0) normal (1, 0, 0) x axis (0, 0, -1)
  circle C1 centre (-39.5442, -25.4558) radius 1.7
extrude "Extrude6" cut sketch "Cam screw clearance (2)" along normal blind 8.2
work_plane "WorkPlane7" AlongDistance 12 ExtraOffset 0
sketch "Cam head recess (2)" plane through (12, 0, 0) normal (1, 0, 0) x axis (0, 0, -1)
  circle C1 centre (-39.5442, -25.4558) radius 3.1
extrude "Extrude7" cut sketch "Cam head recess (2)" along normal blind 3.1
work_plane "WorkPlane1" AlongDistance 0 ExtraOffset 0
sketch "Palm grip smooth contour" plane through (0, 0, 0) normal (1, 0, 0) x axis (0, 0, -1)
  curve K1 (-225, 0) -> (-165, 12)
  line L1 (-225, 0) -> (-165, 0)
  line L2 (-165, 12) -> (-165, 0)
revolve "Revolve1" sketch "Palm grip smooth contour" AlongAngle 360 bodies "P09 Grip insert half"
work_plane "WorkPlane2" AlongDistance 0 ExtraOffset 0
sketch "Split on print bed face" plane through (0, 0, 0) normal (1, 0, 0) x axis (0, 0, -1)
  line L1 (-160, 30) -> (-160, -30)
  line L2 (-230, 30) -> (-160, 30)
  line L3 (-230, -30) -> (-230, 30)
  line L4 (-160, -30) -> (-230, -30)
extrude "Extrude1" cut sketch "Split on print bed face" along normal blind 30
work_plane "WorkPlane3" AlongDistance -7.2 ExtraOffset 0
sketch "Keyed stem socket" plane through (-7.2, 0, 0) normal (1, 0, 0) x axis (0, 0, -1)
  line L1 (-164, 7.2) -> (-164, -7.2)
  line L2 (-196, 7.2) -> (-164, 7.2)
  line L3 (-196, -7.2) -> (-196, 7.2)
  line L4 (-164, -7.2) -> (-196, -7.2)
extrude "Extrude2" cut sketch "Keyed stem socket" along normal blind 14.4
work_plane "WorkPlane4" AlongDistance -13.9 ExtraOffset 0
sketch "M3 grip heat set" plane through (-13.9, 0, 0) normal (1, 0, 0) x axis (0, 0, -1)
  circle C1 centre (-180, 0) radius 1.9
extrude "Extrude3" cut sketch "M3 grip heat set" along normal blind 6.8
work_plane "WorkPlane5" AlongDistance -13.9 ExtraOffset 0
sketch "M3 grip heat set (1)" plane through (-13.9, 0, 0) normal (1, 0, 0) x axis (0, 0, -1)
  circle C1 centre (-190, 0) radius 1.9
extrude "Extrude4" cut sketch "M3 grip heat set (1)" along normal blind 6.8
work_plane "WorkPlane1" AlongDistance 0 ExtraOffset 0
sketch "Palm grip smooth contour" plane through (0, 0, 0) normal (1, 0, 0) x axis (0, 0, -1)
  curve K1 (-225, 0) -> (-165, 12)
  line L1 (-225, 0) -> (-165, 0)
  line L2 (-165, 12) -> (-165, 0)
revolve "Revolve1" sketch "Palm grip smooth contour" AlongAngle 360 bodies "P10 Grip screw half"
work_plane "WorkPlane2" AlongDistance -30 ExtraOffset 0
sketch "Split on print bed face" plane through (-30, 0, 0) normal (1, 0, 0) x axis (0, 0, -1)
  line L1 (-160, 30) -> (-160, -30)
  line L2 (-230, 30) -> (-160, 30)
  line L3 (-230, -30) -> (-230, 30)
  line L4 (-160, -30) -> (-230, -30)
extrude "Extrude1" cut sketch "Split on print bed face" along normal blind 30
work_plane "WorkPlane3" AlongDistance -7.2 ExtraOffset 0
sketch "Keyed stem socket" plane through (-7.2, 0, 0) normal (1, 0, 0) x axis (0, 0, -1)
  line L1 (-164, 7.2) -> (-164, -7.2)
  line L2 (-196, 7.2) -> (-164, 7.2)
  line L3 (-196, -7.2) -> (-196, 7.2)
  line L4 (-164, -7.2) -> (-196, -7.2)
extrude "Extrude2" cut sketch "Keyed stem socket" along normal blind 14.4
work_plane "WorkPlane4" AlongDistance -0.1 ExtraOffset 0
sketch "Grip screw bore" plane through (-0.1, 0, 0) normal (1, 0, 0) x axis (0, 0, -1)
  circle C1 centre (-180, 0) radius 1.7
extrude "Extrude3" cut sketch "Grip screw bore" along normal blind 26
work_plane "WorkPlane5" AlongDistance 12.5 ExtraOffset 0
sketch "Recessed grip screw head" plane through (12.5, 0, 0) normal (1, 0, 0) x axis (0, 0, -1)
  circle C1 centre (-180, 0) radius 3.1
extrude "Extrude4" cut sketch "Recessed grip screw head" along normal blind 14
work_plane "WorkPlane6" AlongDistance -0.1 ExtraOffset 0
sketch "Grip screw bore (1)" plane through (-0.1, 0, 0) normal (1, 0, 0) x axis (0, 0, -1)
  circle C1 centre (-190, 0) radius 1.7
extrude "Extrude5" cut sketch "Grip screw bore (1)" along normal blind 26
work_plane "WorkPlane7" AlongDistance 12.5 ExtraOffset 0
sketch "Recessed grip screw head (1)" plane through (12.5, 0, 0) normal (1, 0, 0) x axis (0, 0, -1)
  circle C1 centre (-190, 0) radius 3.1
extrude "Extrude6" cut sketch "Recessed grip screw head (1)" along normal blind 14
work_plane "WorkPlane1" AlongDistance 4 ExtraOffset 0
sketch "First strong flat cheek" plane through (4, 0, 0) normal (1, 0, 0) x axis (0, 0, -1)
  line L1 (-6, -5) -> (-6, -61)
  line L2 (-7, 0) -> (-6, -5)
  line L3 (-17, 0) -> (-7, 0)
  line L4 (-18, -5) -> (-17, 0)
  line L5 (-18, -61) -> (-18, -5)
  line L6 (-6, -61) -> (-18, -61)
extrude "Extrude1" new body sketch "First strong flat cheek" along normal blind 3 bodies "P11 Forked roller follower"
work_plane "WorkPlane2" AlongDistance 4 ExtraOffset 0
sketch "Spring tail bridge" plane through (4, 0, 0) normal (1, 0, 0) x axis (0, 0, -1)
  line L1 (-6, -49) -> (-6, -61)
  line L2 (-18, -49) -> (-6, -49)
  line L3 (-18, -61) -> (-18, -49)
  line L4 (-6, -61) -> (-18, -61)
extrude "Extrude2" add sketch "Spring tail bridge" along normal blind 16
work_plane "WorkPlane3" AlongDistance 17 ExtraOffset 0
sketch "Second supporting cheek" plane through (17, 0, 0) normal (1, 0, 0) x axis (0, 0, -1)
  line L1 (-6, -5) -> (-6, -61)
  line L2 (-7, 0) -> (-6, -5)
  line L3 (-17, 0) -> (-7, 0)
  line L4 (-18, -5) -> (-17, 0)
  line L5 (-18, -61) -> (-18, -5)
  line L6 (-6, -61) -> (-18, -61)
extrude "Extrude3" add sketch "Second supporting cheek" along normal blind 3
work_plane "WorkPlane4" AlongDistance 4 ExtraOffset 0
sketch "Rounded roller cheek" plane through (4, 0, 0) normal (1, 0, 0) x axis (0, 0, -1)
  circle C1 centre (-12, 0) radius 6
extrude "Extrude4" add sketch "Rounded roller cheek" along normal blind 3
work_plane "WorkPlane5" AlongDistance 17 ExtraOffset 0
sketch "Rounded roller cheek (1)" plane through (17, 0, 0) normal (1, 0, 0) x axis (0, 0, -1)
  circle C1 centre (-12, 0) radius 6
extrude "Extrude5" add sketch "Rounded roller cheek (1)" along normal blind 3
work_plane "WorkPlane6" AlongDistance 3.9 ExtraOffset 0
sketch "Smooth pivot sleeve bore" plane through (3.9, 0, 0) normal (1, 0, 0) x axis (0, 0, -1)
  circle C1 centre (-12, -35) radius 4.15
extrude "Extrude6" cut sketch "Smooth pivot sleeve bore" along normal blind 16.2
work_plane "WorkPlane7" AlongDistance 3.9 ExtraOffset 0
sketch "Roller axle holes" plane through (3.9, 0, 0) normal (1, 0, 0) x axis (0, 0, -1)
  circle C1 centre (-12, 0) radius 1.7
extrude "Extrude7" cut sketch "Roller axle holes" along normal blind 16.2
work_plane "WorkPlane8" AlongDistance 3.9 ExtraOffset 0
sketch "Roller M3 nut recess" plane through (3.9, 0, 0) normal (1, 0, 0) x axis (0, 0, -1)
  line L1 (-14.9, 1.6743) -> (-12, 3.3486)
  line L2 (-14.9, -1.6743) -> (-14.9, 1.6743)
  line L3 (-12, -3.3486) -> (-14.9, -1.6743)
  line L4 (-9.1, -1.6743) -> (-12, -3.3486)
  line L5 (-9.1, 1.6743) -> (-9.1, -1.6743)
  line L6 (-12, 3.3486) -> (-9.1, 1.6743)
extrude "Extrude8" cut sketch "Roller M3 nut recess" along normal blind 1.6
work_plane "WorkPlane9" AlongDistance 18 ExtraOffset 0
sketch "Spring tail locating pilot" plane through (0, 0, 18) normal (0, 0, 1) x axis (1, 0, 0)
  circle C1 centre (12, -55) radius 1.8
extrude "Extrude9" add sketch "Spring tail locating pilot" along normal blind 2
work_plane "WorkPlane1" AlongDistance -24 ExtraOffset 0
sketch "Captured spring reaction block" plane through (-24, 0, 0) normal (1, 0, 0) x axis (0, 0, -1)
  line L1 (-38, -44) -> (-38, -66)
  line L2 (-52, -44) -> (-38, -44)
  line L3 (-52, -66) -> (-52, -44)
  line L4 (-38, -66) -> (-52, -66)
extrude "Extrude1" new body sketch "Captured spring reaction block" along normal blind 48
work_plane "WorkPlane2" AlongDistance -24.1 ExtraOffset 0
sketch "Left M3 insert with screw tip relief" plane through (-24.1, 0, 0) normal (1, 0, 0) x axis (0, 0, -1)
  circle C1 centre (-44, -59) radius 2
extrude "Extrude2" cut sketch "Left M3 insert with screw tip relief" along normal blind 8.8
work_plane "WorkPlane3" AlongDistance 15.3 ExtraOffset 0
sketch "Right M3 insert with screw tip relief" plane through (15.3, 0, 0) normal (1, 0, 0) x axis (0, 0, -1)
  circle C1 centre (-44, -59) radius 2
extrude "Extrude3" cut sketch "Right M3 insert with screw tip relief" along normal blind 8.8
work_plane "WorkPlane4" AlongDistance -24.1 ExtraOffset 0
sketch "Left M3 insert with screw tip relief (1)" plane through (-24.1, 0, 0) normal (1, 0, 0) x axis (0, 0, -1)
  circle C1 centre (-44, -51) radius 2
extrude "Extrude4" cut sketch "Left M3 insert with screw tip relief (1)" along normal blind 8.8
work_plane "WorkPlane5" AlongDistance 15.3 ExtraOffset 0
sketch "Right M3 insert with screw tip relief (1)" plane through (15.3, 0, 0) normal (1, 0, 0) x axis (0, 0, -1)
  circle C1 centre (-44, -51) radius 2
extrude "Extrude5" cut sketch "Right M3 insert with screw tip relief (1)" along normal blind 8.8
work_plane "WorkPlane6" AlongDistance 37.9 ExtraOffset 0
sketch "M4 preload adjuster" plane through (0, 0, 37.9) normal (0, 0, 1) x axis (1, 0, 0)
  circle C1 centre (12, -55) radius 2.2
extrude "Extrude6" cut sketch "M4 preload adjuster" along normal blind 14.2
work_plane "WorkPlane7" AlongDistance 37.9 ExtraOffset 0
sketch "Spring-side loaded retained M4 nut" plane through (0, 0, 37.9) normal (0, 0, 1) x axis (1, 0, 0)
  line L1 (14.1362, -51.3) -> (16.2724, -55)
  line L2 (9.8638, -51.3) -> (14.1362, -51.3)
  line L3 (7.7276, -55) -> (9.8638, -51.3)
  line L4 (9.8638, -58.7) -> (7.7276, -55)
  line L5 (14.1362, -58.7) -> (9.8638, -58.7)
  line L6 (16.2724, -55) -> (14.1362, -58.7)
extrude "Extrude7" cut sketch "Spring-side loaded retained M4 nut" along normal blind 3.5
work_plane "WorkPlane8" AlongDistance 37.9 ExtraOffset 0
sketch "Spring cup guide bolts" plane through (0, 0, 37.9) normal (0, 0, 1) x axis (1, 0, 0)
  circle C1 centre (5, -55) radius 1.7
extrude "Extrude8" cut sketch "Spring cup guide bolts" along normal blind 14.2
work_plane "WorkPlane9" AlongDistance 37.9 ExtraOffset 0
sketch "Spring cup guide bolts (1)" plane through (0, 0, 37.9) normal (0, 0, 1) x axis (1, 0, 0)
  circle C1 centre (19, -55) radius 1.7
extrude "Extrude9" cut sketch "Spring cup guide bolts (1)" along normal blind 14.2
work_plane "WorkPlane11" AlongDistance -18 ExtraOffset 0
sketch "Dedicated thick stop lug" plane through (-18, 0, 0) normal (1, 0, 0) x axis (0, 0, -1)
  line L1 (-72, 5) -> (-72, -5)
  line L2 (-95, 5) -> (-72, 5)
  line L3 (-95, -5) -> (-95, 5)
  line L4 (-72, -5) -> (-95, -5)
extrude "Extrude11" add sketch "Dedicated thick stop lug" along normal blind 11.5
work_plane "WorkPlane12" AlongDistance -18 ExtraOffset 0
sketch "Rounded stop contact" plane through (-18, 0, 0) normal (1, 0, 0) x axis (0, 0, -1)
  circle C1 centre (-95, 0) radius 5
extrude "Extrude12" add sketch "Rounded stop contact" along normal blind 11.5
work_plane "WorkPlane10" AlongDistance -36 ExtraOffset 0
sketch "Broad stop support ear" plane through (-36, 0, 0) normal (1, 0, 0) x axis (0, 0, -1)
  line L1 (-60, -20) -> (-60, -44)
  line L2 (-90, -20) -> (-60, -20)
  line L3 (-90, -44) -> (-90, -20)
  line L4 (-60, -44) -> (-90, -44)
extrude "Extrude10" add sketch "Broad stop support ear" along normal blind 12
work_plane "WorkPlane11" AlongDistance -24 ExtraOffset 0
sketch "Integrated steel-core end stop" plane through (-24, 0, 0) normal (1, 0, 0) x axis (0, 0, -1)
  circle C1 centre (-79.6754, -33.9652) radius 6
extrude "Extrude11" add sketch "Integrated steel-core end stop" along normal blind 15
work_plane "WorkPlane12" AlongDistance -36.1 ExtraOffset 0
